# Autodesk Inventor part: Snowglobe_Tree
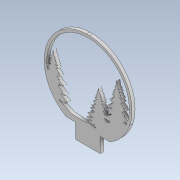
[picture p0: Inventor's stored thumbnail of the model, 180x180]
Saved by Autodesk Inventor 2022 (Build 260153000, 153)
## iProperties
Created: 2021-12
Part Number: Snowglobe_Tree
Material: Generic
Document SubType Name: Modeling
Designer: allis
Density: 1 g/cm^3
Appearance: Default
Author: allis
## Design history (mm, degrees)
sketch "Sketch3"
  geometry: L1 (88.095, -64.197)-(88.278, -64.559); L2 (88.278, -64.559)-(88.491, -64.713); L3 (88.491, -64.713)-(88.714, -64.861); L4 (88.714, -64.861)-(89.007, -65.055); L5 (89.007, -65.055)-(89.317, -65.231); L6 (89.317, -65.231)-(89.583, -65.458); L7 (89.583, -65.458)-(89.898, -65.727); L8 (89.898, -65.727)-(89.819, -66.127); L9 (89.819, -66.127)-(89.437, -66.198); L10 (89.437, -66.198)-(88.703, -66.335); L11 (88.703, -66.335)-(87.958, -66.464); L12 (87.958, -66.464)-(87.263, -66.022); L13 (87.263, -66.022)-(87.179, -65.969); L14 (87.179, -65.969)-(87.077, -65.883); L15 (87.077, -65.883)-(86.931, -66.019); L16 (86.931, -66.019)-(87.204, -66.392); L17 (87.204, -66.392)-(87.512, -66.729); L18 (87.512, -66.729)-(87.879, -67.014); L19 (87.879, -67.014)-(88.082, -67.172); L20 (88.082, -67.172)-(88.296, -67.224); L21 (88.296, -67.224)-(88.551, -67.154); L22 (88.551, -67.154)-(88.862, -67.069); L23 (88.862, -67.069)-(89.181, -67.01); L24 (89.181, -67.01)-(89.497, -66.938); L25 (89.497, -66.938)-(89.686, -66.894); L26 (89.686, -66.894)-(89.829, -66.797); L27 (89.829, -66.797)-(89.899, -66.604); L28 (89.899, -66.604)-(90.036, -66.219); L29 (90.036, -66.219)-(90.181, -65.837); L30 (90.181, -65.837)-(90.322, -65.455); L31 (90.322, -65.455)-(90.375, -65.31); L32 (90.375, -65.31)-(90.388, -65.181); L33 (90.388, -65.181)-(90.211, -65.105); L34 (90.211, -65.105)-(89.541, -64.82); L35 (89.541, -64.82)-(88.873, -64.531); L36 (88.873, -64.531)-(88.095, -64.197); L37 (10.248, -55.142)-(9.954, -55.216); L38 (9.954, -55.216)-(9.673, -55.284); L39 (9.673, -55.284)-(9.394, -55.358); L40 (9.394, -55.358)-(9.247, -55.397); L41 (9.247, -55.397)-(9.255, -55.522); L42 (9.255, -55.522)-(9.269, -55.633); L43 (9.269, -55.633)-(9.334, -56.177); L44 (9.334, -56.177)-(9.41, -56.718); L45 (9.41, -56.718)-(9.47, -57.262); L46 (9.47, -57.262)-(9.507, -57.601); L47 (9.507, -57.601)-(9.718, -57.708); L48 (9.718, -57.708)-(9.999, -57.62); L49 (9.999, -57.62)-(10.706, -57.398); L50 (10.706, -57.398)-(11.32, -57.009); L51 (11.32, -57.009)-(11.845, -56.485); L52 (11.845, -56.485)-(11.919, -56.412); L53 (11.919, -56.412)-(11.968, -56.252); L54 (11.968, -56.252)-(11.831, -56.269); L55 (11.831, -56.269)-(11.393, -56.324); L56 (11.393, -56.324)-(11.119, -55.958); L57 (11.119, -55.958)-(10.731, -55.898); L58 (10.731, -55.898)-(10.153, -55.808); L59 (10.153, -55.808)-(10.088, -55.698); L60 (10.088, -55.698)-(10.248, -55.142); L61 (67.318, -72.277)-(67.449, -72.614); L62 (67.449, -72.614)-(67.645, -72.733); L63 (67.645, -72.733)-(67.825, -72.86); L64 (67.825, -72.86)-(68.448, -73.298)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; 1 further point
  constraints: 7 other
extrude "Extrusion2" join sketch "Sketch3" distance "d3" = 3.175; taper "d4" = 0 deg
body "Solid1"
